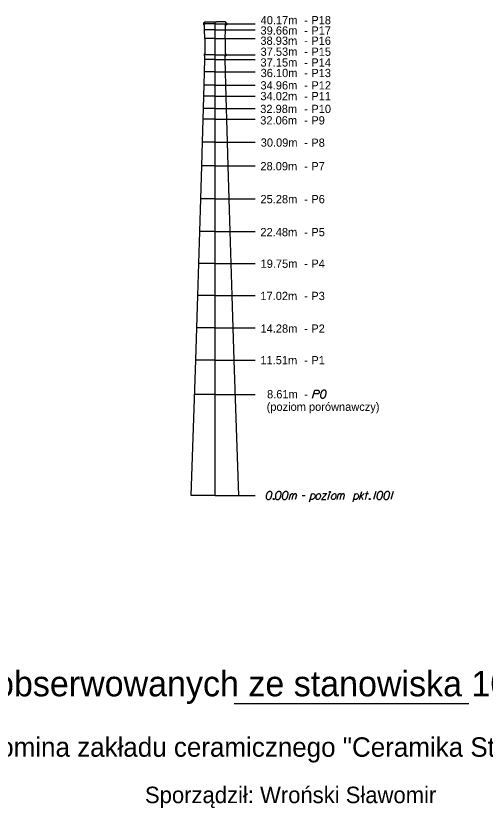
# Model space of a CAD drawing. Extents: x 138 to 264, y -75 to 121.
# Drawn here: x 237.9 to 246.67, y 84.49 to 99.29 of the extents above; entities that cross this region are included whole.
import ezdxf

# ---------------------------------------------------------------- set-up
doc = ezdxf.new("R2010")
doc.units = 0
doc.layers.add('Opisy', color=7, linetype='Continuous')

msp = doc.modelspace()

# ---------------------------------------------------------------- linework, layer by layer
at = {"layer": 'Opisy'}
for p, q in [((241.411, 99.16), (241.411, 99.141)), ((241.427, 99.16), (241.411, 99.16)), ((241.624, 99.141), (241.411, 99.141)), ((241.411, 99.141), (241.411, 99.122)), ((241.427, 99.122), (241.411, 99.122)), ((241.427, 99.178), (241.427, 99.16)), ((241.427, 99.178), (241.654, 99.178)), ((241.427, 99.028), (241.427, 99.122)), ((241.624, 90.332), (241.624, 99.178)), ((241.624, 99.141), (242.377, 99.141)), ((241.82, 99.178), (241.654, 99.178)), ((241.82, 99.178), (241.82, 99.16)), ((241.82, 99.16), (241.836, 99.16)), ((241.82, 99.122), (241.836, 99.122)), ((241.82, 99.028), (241.82, 99.122)), ((241.836, 99.16), (241.836, 99.141)), ((241.836, 99.141), (241.836, 99.122)), ((241.624, 99.028), (241.427, 99.028)), ((241.434, 98.868), (241.427, 99.028)), ((241.624, 99.028), (242.377, 99.028)), ((241.813, 98.868), (241.82, 99.028)), ((241.624, 98.868), (241.434, 98.868)), ((241.434, 98.868), (241.434, 98.58)), ((241.624, 98.868), (242.377, 98.868)), ((241.813, 98.868), (241.813, 98.58)), ((241.421, 98.58), (241.421, 98.561)), ((241.421, 98.58), (241.434, 98.58)), ((241.624, 98.561), (241.421, 98.561)), ((241.421, 98.561), (241.421, 98.542)), ((241.436, 98.542), (241.421, 98.542)), ((241.427, 98.247), (241.434, 98.478)), ((241.434, 98.478), (241.436, 98.542)), ((241.624, 98.478), (241.434, 98.478)), ((241.624, 98.561), (242.377, 98.561)), ((241.624, 98.478), (242.377, 98.478)), ((241.813, 98.478), (241.811, 98.542)), ((241.811, 98.542), (241.826, 98.542)), ((241.826, 98.58), (241.813, 98.58)), ((241.82, 98.247), (241.813, 98.478)), ((241.826, 98.58), (241.826, 98.561)), ((241.826, 98.561), (241.826, 98.542)), ((241.421, 97.997), (241.427, 98.247)), ((241.624, 98.247), (241.427, 98.247)), ((241.624, 98.247), (242.377, 98.247)), ((241.826, 97.997), (241.82, 98.247)), ((241.414, 97.791), (241.421, 97.997)), ((241.624, 97.997), (241.421, 97.997)), ((241.624, 97.997), (242.377, 97.997)), ((241.833, 97.791), (241.826, 97.997)), ((241.409, 97.563), (241.414, 97.791)), ((241.624, 97.791), (241.414, 97.791)), ((241.624, 97.791), (242.377, 97.791)), ((241.838, 97.563), (241.833, 97.791)), ((241.401, 97.361), (241.409, 97.563)), ((241.624, 97.563), (241.409, 97.563)), ((241.624, 97.563), (242.377, 97.563)), ((241.846, 97.361), (241.838, 97.563)), ((241.389, 96.929), (241.401, 97.361)), ((241.624, 97.361), (241.401, 97.361)), ((241.624, 97.361), (242.377, 97.361)), ((241.858, 96.929), (241.846, 97.361)), ((241.376, 96.491), (241.389, 96.929)), ((241.624, 96.929), (241.389, 96.929)), ((241.624, 96.929), (242.377, 96.929)), ((241.871, 96.491), (241.858, 96.929)), ((241.358, 95.874), (241.376, 96.491)), ((241.624, 96.491), (241.376, 96.491)), ((241.624, 96.491), (242.377, 96.491)), ((241.889, 95.874), (241.871, 96.491)), ((241.339, 95.261), (241.358, 95.874)), ((241.624, 95.874), (241.358, 95.874)), ((241.624, 95.874), (242.377, 95.874)), ((241.909, 95.261), (241.889, 95.874)), ((241.32, 94.662), (241.339, 95.261)), ((241.624, 95.261), (241.339, 95.261)), ((241.624, 95.261), (242.377, 95.261)), ((241.927, 94.662), (241.909, 95.261)), ((241.301, 94.064), (241.32, 94.662)), ((241.624, 94.662), (241.32, 94.662)), ((241.624, 94.662), (242.377, 94.662)), ((241.946, 94.064), (241.927, 94.662)), ((241.283, 93.462), (241.301, 94.064)), ((241.624, 94.064), (241.301, 94.064)), ((241.624, 94.064), (242.377, 94.064)), ((241.965, 93.462), (241.946, 94.064)), ((241.263, 92.856), (241.283, 93.462)), ((241.624, 93.462), (241.283, 93.462)), ((241.624, 93.462), (242.377, 93.462)), ((241.984, 92.856), (241.965, 93.462)), ((241.18, 90.332), (241.263, 92.856)), ((241.624, 92.856), (241.263, 92.856)), ((241.624, 92.856), (242.377, 92.856)), ((242.067, 90.332), (241.984, 92.856)), ((241.624, 92.219), (241.242, 92.219)), ((241.624, 92.219), (242.377, 92.219)), ((241.624, 90.332), (241.18, 90.332)), ((241.624, 90.332), (242.377, 90.332)), ((241.984, 86.444), (246.368, 86.444))]:
    msp.add_line(p, q, dxfattribs=at)
for points in [[(243.446, 92.145), (243.487, 92.299), (243.539, 92.299), (243.547, 92.298), (243.55, 92.296), (243.557, 92.293), (243.562, 92.289), (243.566, 92.284), (243.57, 92.278), (243.572, 92.27), (243.573, 92.262), (243.572, 92.256), (243.571, 92.251), (243.568, 92.247), (243.566, 92.243), (243.562, 92.238), (243.557, 92.234), (243.554, 92.232), (243.548, 92.23), (243.542, 92.228), (243.469, 92.228)], [(243.667, 92.299), (243.664, 92.299), (243.657, 92.298), (243.652, 92.296), (243.649, 92.295), (243.642, 92.293), (243.635, 92.289), (243.629, 92.285), (243.623, 92.281), (243.619, 92.276), (243.616, 92.27), (243.612, 92.264), (243.608, 92.256), (243.606, 92.251), (243.604, 92.244), (243.6, 92.232), (243.596, 92.214), (243.594, 92.199), (243.594, 92.186), (243.595, 92.176), (243.6, 92.165), (243.604, 92.159), (243.61, 92.152), (243.617, 92.147), (243.621, 92.146), (243.628, 92.145), (243.634, 92.145), (243.644, 92.146), (243.652, 92.148), (243.658, 92.152), (243.667, 92.158), (243.67, 92.162), (243.675, 92.166), (243.679, 92.171), (243.681, 92.175), (243.684, 92.181), (243.685, 92.183), (243.687, 92.19), (243.69, 92.197), (243.692, 92.204), (243.693, 92.209), (243.695, 92.213), (243.696, 92.217), (243.698, 92.228), (243.699, 92.234), (243.701, 92.24), (243.702, 92.249), (243.703, 92.26), (243.703, 92.264), (243.702, 92.268), (243.701, 92.273), (243.697, 92.281), (243.693, 92.285), (243.69, 92.289), (243.685, 92.293), (243.68, 92.295), (243.676, 92.296), (243.673, 92.298), (243.667, 92.299)], [(242.653, 90.406), (242.65, 90.406), (242.643, 90.405), (242.638, 90.404), (242.635, 90.403), (242.629, 90.4), (242.621, 90.397), (242.615, 90.393), (242.609, 90.388), (242.606, 90.383), (242.602, 90.377), (242.598, 90.371), (242.595, 90.364), (242.592, 90.359), (242.59, 90.352), (242.586, 90.34), (242.582, 90.321), (242.58, 90.307), (242.58, 90.293), (242.581, 90.284), (242.586, 90.273), (242.59, 90.267), (242.596, 90.259), (242.603, 90.255), (242.607, 90.253), (242.614, 90.252), (242.62, 90.252), (242.63, 90.253), (242.638, 90.256), (242.644, 90.259), (242.653, 90.266), (242.657, 90.269), (242.661, 90.274), (242.665, 90.279), (242.667, 90.283), (242.67, 90.289), (242.671, 90.291), (242.674, 90.297), (242.676, 90.304), (242.678, 90.312), (242.68, 90.317), (242.681, 90.32), (242.682, 90.325), (242.684, 90.336), (242.686, 90.342), (242.687, 90.348), (242.688, 90.357), (242.689, 90.367), (242.689, 90.371), (242.688, 90.376), (242.687, 90.381), (242.683, 90.388), (242.68, 90.393), (242.676, 90.397), (242.671, 90.4), (242.666, 90.403), (242.663, 90.404), (242.659, 90.405), (242.653, 90.406)], [(242.824, 90.406), (242.822, 90.406), (242.814, 90.405), (242.809, 90.404), (242.806, 90.403), (242.8, 90.4), (242.792, 90.397), (242.786, 90.393), (242.78, 90.388), (242.777, 90.383), (242.773, 90.377), (242.769, 90.371), (242.766, 90.364), (242.763, 90.359), (242.761, 90.352), (242.757, 90.34), (242.754, 90.321), (242.751, 90.307), (242.751, 90.293), (242.752, 90.284), (242.757, 90.273), (242.761, 90.267), (242.767, 90.259), (242.774, 90.255), (242.778, 90.253), (242.785, 90.252), (242.791, 90.252), (242.801, 90.253), (242.809, 90.256), (242.816, 90.259), (242.824, 90.266), (242.828, 90.269), (242.833, 90.274), (242.836, 90.279), (242.839, 90.283), (242.841, 90.289), (242.842, 90.291), (242.845, 90.297), (242.847, 90.304), (242.849, 90.312), (242.851, 90.317), (242.852, 90.32), (242.853, 90.325), (242.856, 90.336), (242.857, 90.342), (242.858, 90.348), (242.859, 90.357), (242.86, 90.367), (242.86, 90.371), (242.859, 90.376), (242.858, 90.381), (242.854, 90.388), (242.851, 90.393), (242.847, 90.397), (242.842, 90.4), (242.837, 90.403), (242.834, 90.404), (242.83, 90.405), (242.824, 90.406)], [(242.954, 90.406), (242.951, 90.406), (242.944, 90.405), (242.939, 90.404), (242.936, 90.403), (242.93, 90.4), (242.922, 90.397), (242.916, 90.393), (242.91, 90.388), (242.907, 90.383), (242.903, 90.377), (242.899, 90.371), (242.896, 90.364), (242.893, 90.359), (242.891, 90.352), (242.887, 90.34), (242.883, 90.321), (242.881, 90.307), (242.881, 90.293), (242.882, 90.284), (242.887, 90.273), (242.891, 90.267), (242.897, 90.259), (242.904, 90.255), (242.908, 90.253), (242.915, 90.252), (242.921, 90.252), (242.931, 90.253), (242.939, 90.256), (242.945, 90.259), (242.954, 90.266), (242.958, 90.269), (242.962, 90.274), (242.966, 90.279), (242.968, 90.283), (242.971, 90.289), (242.972, 90.291), (242.975, 90.297), (242.977, 90.304), (242.979, 90.312), (242.981, 90.317), (242.982, 90.32), (242.983, 90.325), (242.985, 90.336), (242.987, 90.342), (242.988, 90.348), (242.989, 90.357), (242.99, 90.367), (242.99, 90.371), (242.989, 90.376), (242.988, 90.381), (242.984, 90.388), (242.981, 90.393), (242.977, 90.397), (242.972, 90.4), (242.967, 90.403), (242.964, 90.404), (242.96, 90.405), (242.954, 90.406)], [(243.011, 90.252), (243.039, 90.363)], [(243.032, 90.333), (243.038, 90.347), (243.044, 90.354), (243.051, 90.359), (243.058, 90.363), (243.063, 90.365), (243.07, 90.365), (243.073, 90.364), (243.078, 90.359), (243.083, 90.353), (243.086, 90.342), (243.087, 90.336), (243.093, 90.347), (243.101, 90.354), (243.108, 90.359), (243.115, 90.363), (243.121, 90.365), (243.127, 90.365), (243.132, 90.364), (243.136, 90.359), (243.14, 90.353), (243.143, 90.342), (243.144, 90.336), (243.124, 90.252)], [(243.067, 90.252), (243.087, 90.336)], [(243.254, 90.33), (243.306, 90.33)], [(243.389, 90.212), (243.43, 90.364)], [(243.426, 90.35), (243.438, 90.36), (243.457, 90.364), (243.471, 90.361), (243.481, 90.354), (243.488, 90.344), (243.493, 90.331), (243.494, 90.319), (243.492, 90.308), (243.488, 90.295), (243.478, 90.28), (243.466, 90.267), (243.448, 90.255), (243.432, 90.252), (243.418, 90.253), (243.402, 90.262)], [(243.562, 90.364), (243.571, 90.364), (243.58, 90.359), (243.59, 90.346), (243.591, 90.34), (243.592, 90.333), (243.592, 90.329), (243.592, 90.31), (243.589, 90.298), (243.583, 90.284), (243.575, 90.272), (243.563, 90.261), (243.552, 90.252), (243.534, 90.252), (243.527, 90.255), (243.52, 90.261), (243.516, 90.267), (243.511, 90.281), (243.511, 90.303), (243.514, 90.31), (243.518, 90.326), (243.523, 90.335), (243.526, 90.34), (243.538, 90.353), (243.55, 90.36), (243.562, 90.364)], [(243.635, 90.366), (243.714, 90.366), (243.613, 90.252), (243.691, 90.252)], [(243.734, 90.252), (243.766, 90.37)], [(243.768, 90.406), (243.775, 90.406), (243.778, 90.404), (243.782, 90.399), (243.782, 90.393), (243.778, 90.388), (243.775, 90.386), (243.768, 90.386), (243.765, 90.388), (243.761, 90.393), (243.761, 90.399), (243.765, 90.404), (243.768, 90.406)], [(243.853, 90.364), (243.862, 90.364), (243.872, 90.359), (243.881, 90.346), (243.883, 90.34), (243.884, 90.333), (243.884, 90.329), (243.884, 90.31), (243.88, 90.298), (243.874, 90.284), (243.867, 90.272), (243.855, 90.261), (243.844, 90.252), (243.826, 90.252), (243.818, 90.255), (243.811, 90.261), (243.807, 90.267), (243.802, 90.281), (243.802, 90.303), (243.805, 90.31), (243.81, 90.326), (243.815, 90.335), (243.817, 90.34), (243.829, 90.353), (243.841, 90.36), (243.853, 90.364)], [(243.904, 90.252), (243.932, 90.363)], [(243.925, 90.333), (243.931, 90.347), (243.937, 90.354), (243.944, 90.359), (243.952, 90.363), (243.957, 90.365), (243.964, 90.365), (243.966, 90.364), (243.971, 90.359), (243.976, 90.353), (243.98, 90.342), (243.981, 90.336), (243.987, 90.347), (243.994, 90.354), (244.002, 90.359), (244.009, 90.363), (244.015, 90.365), (244.021, 90.365), (244.026, 90.364), (244.029, 90.359), (244.033, 90.353), (244.037, 90.342), (244.038, 90.336), (244.017, 90.252)], [(243.96, 90.252), (243.981, 90.336)], [(244.202, 90.212), (244.243, 90.364)], [(244.239, 90.35), (244.252, 90.36), (244.27, 90.364), (244.284, 90.361), (244.294, 90.354), (244.301, 90.344), (244.306, 90.331), (244.307, 90.319), (244.305, 90.308), (244.301, 90.295), (244.292, 90.28), (244.28, 90.267), (244.261, 90.255), (244.246, 90.252), (244.231, 90.253), (244.215, 90.262)], [(244.324, 90.252), (244.366, 90.406)], [(244.339, 90.307), (244.412, 90.367)], [(244.354, 90.319), (244.385, 90.252)], [(244.432, 90.252), (244.473, 90.406)], [(244.432, 90.364), (244.491, 90.364)], [(244.628, 90.406), (244.587, 90.252)], [(244.721, 90.406), (244.719, 90.406), (244.712, 90.405), (244.707, 90.404), (244.703, 90.403), (244.697, 90.4), (244.69, 90.397), (244.684, 90.393), (244.678, 90.388), (244.674, 90.383), (244.67, 90.377), (244.667, 90.371), (244.663, 90.364), (244.661, 90.359), (244.658, 90.352), (244.655, 90.34), (244.651, 90.321), (244.648, 90.307), (244.648, 90.293), (244.65, 90.284), (244.655, 90.273), (244.658, 90.267), (244.664, 90.259), (244.672, 90.255), (244.675, 90.253), (244.682, 90.252), (244.689, 90.252), (244.698, 90.253), (244.707, 90.256), (244.713, 90.259), (244.721, 90.266), (244.725, 90.269), (244.73, 90.274), (244.733, 90.279), (244.736, 90.283), (244.738, 90.289), (244.74, 90.291), (244.742, 90.297), (244.744, 90.304), (244.747, 90.312), (244.748, 90.317), (244.749, 90.32), (244.75, 90.325), (244.753, 90.336), (244.754, 90.342), (244.755, 90.348), (244.757, 90.357), (244.758, 90.367), (244.758, 90.371), (244.757, 90.376), (244.755, 90.381), (244.752, 90.388), (244.748, 90.393), (244.744, 90.397), (244.74, 90.4), (244.735, 90.403), (244.731, 90.404), (244.727, 90.405), (244.721, 90.406)], [(244.851, 90.406), (244.849, 90.406), (244.841, 90.405), (244.837, 90.404), (244.833, 90.403), (244.827, 90.4), (244.82, 90.397), (244.814, 90.393), (244.807, 90.388), (244.804, 90.383), (244.8, 90.377), (244.797, 90.371), (244.793, 90.364), (244.79, 90.359), (244.788, 90.352), (244.784, 90.34), (244.781, 90.321), (244.778, 90.307), (244.778, 90.293), (244.78, 90.284), (244.784, 90.273), (244.788, 90.267), (244.794, 90.259), (244.801, 90.255), (244.805, 90.253), (244.812, 90.252), (244.818, 90.252), (244.828, 90.253), (244.837, 90.256), (244.843, 90.259), (244.851, 90.266), (244.855, 90.269), (244.86, 90.274), (244.863, 90.279), (244.866, 90.283), (244.868, 90.289), (244.869, 90.291), (244.872, 90.297), (244.874, 90.304), (244.877, 90.312), (244.878, 90.317), (244.879, 90.32), (244.88, 90.325), (244.883, 90.336), (244.884, 90.342), (244.885, 90.348), (244.886, 90.357), (244.888, 90.367), (244.888, 90.371), (244.886, 90.376), (244.885, 90.381), (244.882, 90.388), (244.878, 90.393), (244.874, 90.397), (244.869, 90.4), (244.865, 90.403), (244.861, 90.404), (244.857, 90.405), (244.851, 90.406)], [(244.949, 90.406), (244.908, 90.252)], [(242.717, 90.273), (242.723, 90.273), (242.727, 90.27), (242.731, 90.266), (242.731, 90.259), (242.727, 90.255), (242.723, 90.252), (242.717, 90.252), (242.714, 90.255), (242.71, 90.259), (242.71, 90.266), (242.714, 90.27), (242.717, 90.273)], [(244.511, 90.273), (244.517, 90.273), (244.521, 90.27), (244.525, 90.266), (244.525, 90.259), (244.521, 90.255), (244.517, 90.252), (244.511, 90.252), (244.508, 90.255), (244.504, 90.259), (244.504, 90.266), (244.508, 90.27), (244.511, 90.273)]]:
    msp.add_lwpolyline(points, dxfattribs=at)

# ---------------------------------------------------------------- texts
for s, height, p in [('40.17m', 0.1542, (242.476, 99.135)), ('-', 0.154, (243.287, 99.135)), ('P18', 0.1542, (243.423, 99.135)), ('39.66m', 0.1542, (242.474, 98.941)), ('P17', 0.1542, (243.424, 98.941)), ('38.93m', 0.1542, (242.472, 98.75)), ('-', 0.154, (243.288, 98.941)), ('P16', 0.1542, (243.423, 98.75)), ('-', 0.154, (243.291, 98.75)), ('37.53m', 0.1542, (242.475, 98.545)), ('-', 0.154, (243.287, 98.545)), ('P15', 0.1542, (243.424, 98.545)), ('37.15m', 0.1542, (242.473, 98.344)), ('P14', 0.1542, (243.423, 98.344)), ('36.10m', 0.1542, (242.476, 98.147)), ('-', 0.154, (243.287, 98.344)), ('P13', 0.1542, (243.423, 98.147)), ('-', 0.154, (243.288, 98.147)), ('34.96m', 0.1542, (242.473, 97.916)), ('P12', 0.1542, (243.424, 97.916)), ('34.02m', 0.1542, (242.472, 97.715)), ('-', 0.154, (243.288, 97.916)), ('P11', 0.1542, (243.423, 97.715)), ('-', 0.154, (243.288, 97.715)), ('32.98m', 0.1542, (242.469, 97.476)), ('P10', 0.1542, (243.424, 97.476)), ('32.06m', 0.1542, (242.469, 97.262)), ('-', 0.154, (243.288, 97.476)), ('P9', 0.1542, (243.423, 97.262)), ('-', 0.154, (243.288, 97.262)), ('30.09m', 0.1542, (242.478, 96.847)), ('P8', 0.1542, (243.423, 96.845)), ('-', 0.154, (243.288, 96.847)), ('28.09m', 0.1542, (242.472, 96.406)), ('P7', 0.1542, (243.423, 96.406)), ('-', 0.154, (243.288, 96.406)), ('25.28m', 0.1542, (242.473, 95.79)), ('P6', 0.1542, (243.423, 95.79)), ('-', 0.154, (243.287, 95.79)), ('22.48m', 0.1542, (242.472, 95.174)), ('-', 0.154, (243.287, 95.174)), ('P5', 0.1542, (243.424, 95.174)), ('19.75m', 0.1542, (242.475, 94.584)), ('-', 0.154, (243.287, 94.584)), ('P4', 0.1542, (243.424, 94.584)), ('17.02m', 0.1542, (242.472, 93.981)), ('-', 0.154, (243.287, 93.981)), ('P3', 0.1542, (243.423, 93.981)), ('14.28m', 0.1542, (242.474, 93.371)), ('-', 0.154, (243.287, 93.371)), ('P2', 0.1542, (243.423, 93.371)), ('11.51m', 0.1542, (242.472, 92.781)), ('-', 0.154, (243.287, 92.781)), ('P1', 0.1542, (243.424, 92.781)), ('8.61m', 0.1542, (242.596, 92.145)), ('-', 0.154, (243.287, 92.145)), ('(poziom porównawczy)', 0.15416, (242.589, 91.911)), ('Wykres wychyleń osi komina obserwowanych ze stanowiska 1002', 0.47516, (229.217, 86.577)), ('Badanie pionowości i prostoliniowości komina zakładu ceramicznego "Ceramika Stróże"', 0.36281, (229.098, 85.448)), ('Sporządził: Wroński Sławomir', 0.30766, (240.316, 84.581))]:
    msp.add_text(s, height=height, dxfattribs=at).set_placement(p)

doc.saveas('drawing.dxf')
